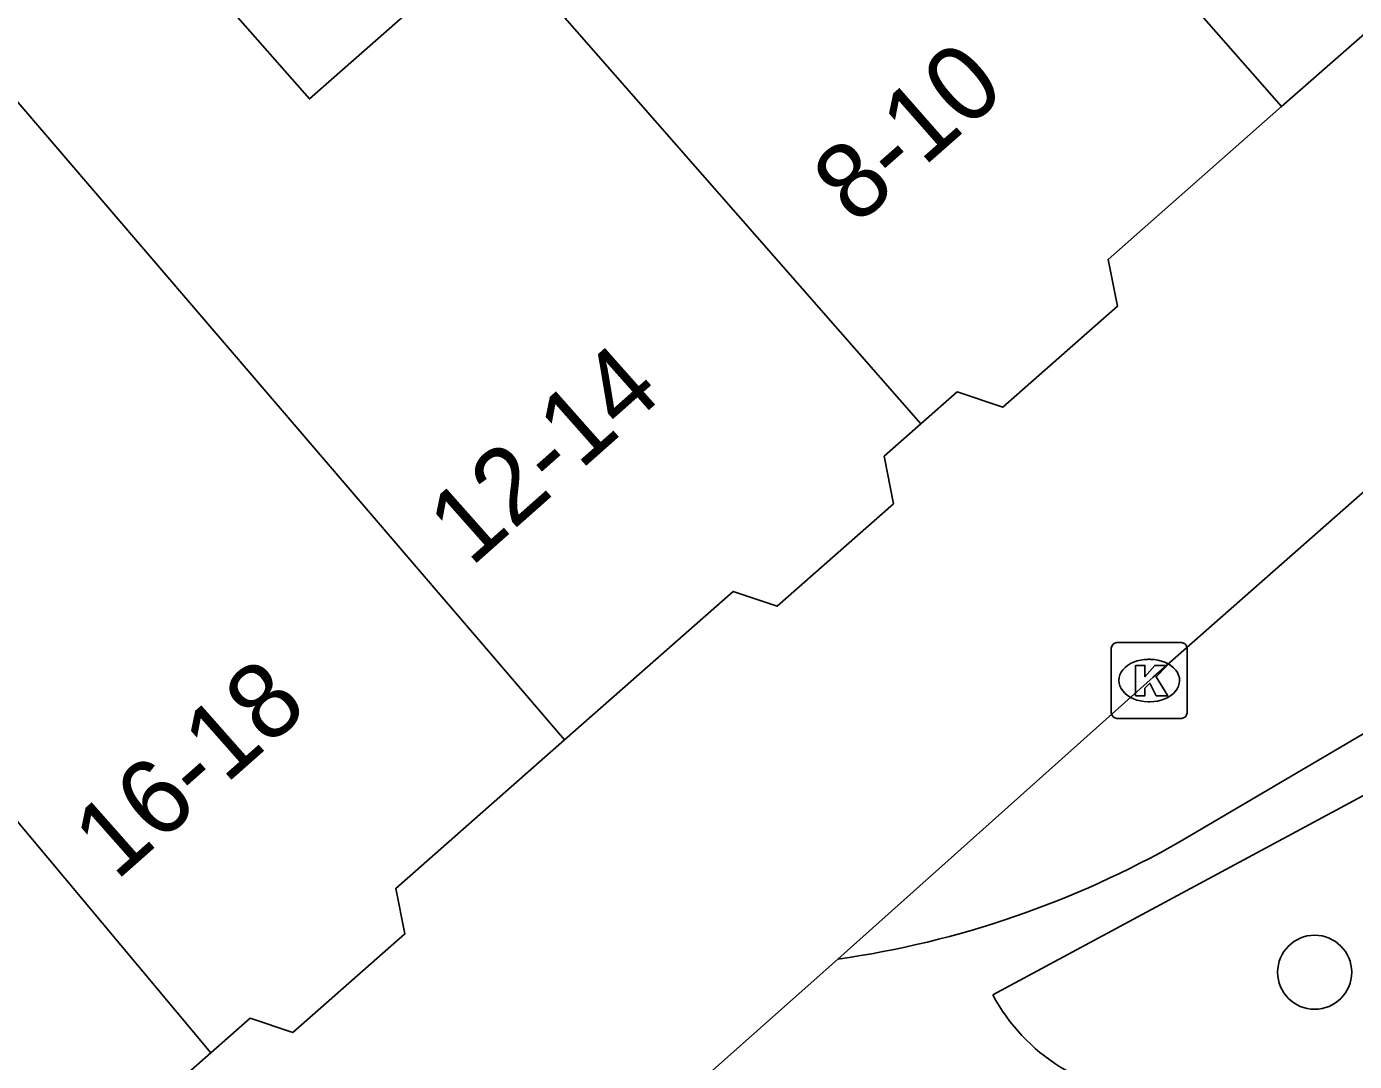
# Model space of a CAD drawing. Extents: x 159961 to 160856, y 382704 to 383353.
# Drawn here: x 160523.05 to 160540.59, y 383049.52 to 383063.19 of the extents above; entities that cross this region are included whole.
import ezdxf

# ---------------------------------------------------------------- set-up
doc = ezdxf.new("R2010")
doc.units = 0
for name, color, linetype in [('IMGEO_Boom', 7, 'Continuous'), ('IMGEO_Kolk', 7, 'Continuous'), ('IMGEO_Pand', 7, 'Continuous'), ('IMGEO_Pand_nummerreeks', 7, 'Continuous'), ('IMGEO_Voetpad_open', 7, 'Continuous')]:
    doc.layers.add(name, color=color, linetype=linetype)

msp = doc.modelspace()

# ---------------------------------------------------------------- linework, layer by layer
at = {"layer": 'IMGEO_Boom'}
msp.add_circle((160540.068, 383050.7), 0.489, dxfattribs=at)
at = {"layer": 'IMGEO_Kolk'}
for p, q in [((160537.382, 383054.127), (160537.382, 383054.979)), ((160537.457, 383055.053), (160538.309, 383055.053)), ((160538.383, 383054.979), (160538.383, 383054.127)), ((160537.87, 383054.833), (160537.895, 383054.833)), ((160537.893, 383054.273), (160537.868, 383054.273)), ((160538.309, 383054.053), (160537.457, 383054.053))]:
    msp.add_line(p, q, dxfattribs=at)
for points in [[(160537.382, 383054.127), (160537.382, 383054.979)], [(160537.457, 383055.053), (160538.309, 383055.053)], [(160538.383, 383054.979), (160538.383, 383054.127)], [(160537.703, 383054.753), (160537.826, 383054.753), (160537.826, 383054.602), (160537.956, 383054.753), (160538.12, 383054.753), (160537.974, 383054.602), (160538.127, 383054.353), (160537.975, 383054.353), (160537.89, 383054.517), (160537.826, 383054.45), (160537.826, 383054.353), (160537.703, 383054.353), (160537.703, 383054.753)], [(160538.309, 383054.053), (160537.457, 383054.053)]]:
    msp.add_lwpolyline(points, dxfattribs=at)
for centre, start, end in [((160537.459, 383054.977), 91.552, 178.448), ((160537.459, 383054.977), 91.552, 178.448), ((160538.307, 383054.977), 1.552, 88.448), ((160538.307, 383054.977), 1.552, 88.448), ((160537.459, 383054.129), 181.552, 268.448), ((160537.459, 383054.129), 181.552, 268.448), ((160538.307, 383054.129), 271.552, 358.448), ((160538.307, 383054.129), 271.552, 358.448)]:
    msp.add_arc(centre, 0.0765, start, end, dxfattribs=at)
for centre, major_axis, ratio, start_param, end_param in [((160537.869, 383054.553), (-0.387, 0.002), 0.722429, 4.712389, 7.853982), ((160537.894, 383054.553), (-0.39, 0.002), 0.717154, 1.570796, 4.712389)]:
    msp.add_ellipse(centre, major_axis=major_axis, ratio=ratio, start_param=start_param, end_param=end_param, dxfattribs=at)
at = {"layer": 'IMGEO_Pand'}
for points in [[(160530.268, 383072.789), (160539.632, 383062.132)], [(160520.95, 383064.512), (160523.35, 383066.624), (160525.951, 383063.668), (160525.713, 383063.459), (160526.791, 383062.234), (160529.228, 383064.379)], [(160539.632, 383062.132), (160541.437, 383063.72), (160542.131, 383062.942), (160545.173, 383065.602)], [(160530.16, 383053.768), (160520.95, 383064.512)], [(160534.867, 383057.942), (160529.228, 383064.379)], [(160534.867, 383057.942), (160535.348, 383058.365), (160535.948, 383058.162), (160537.465, 383059.497), (160537.34, 383060.115), (160539.632, 383062.132)], [(160530.16, 383053.768), (160532.388, 383055.729), (160532.968, 383055.534), (160534.507, 383056.888), (160534.381, 383057.514), (160534.867, 383057.942)], [(160519.966, 383056.235), (160525.489, 383049.638)], [(160525.489, 383049.638), (160526.007, 383050.093), (160526.57, 383049.903), (160528.052, 383051.207), (160527.931, 383051.807), (160530.16, 383053.768)], [(160520.78, 383045.465), (160523.013, 383047.43), (160523.572, 383047.241), (160525.053, 383048.545), (160524.932, 383049.148), (160525.489, 383049.638)]]:
    msp.add_lwpolyline(points, dxfattribs=at)
at = {"layer": 'IMGEO_Voetpad_open'}
for points in [[(160542.574, 383058.683), (160537.937, 383054.599), (160533.771, 383050.874)], [(160541.572, 383054.355), (160538.29, 383052.426)], [(160535.818, 383050.401), (160541.107, 383053.247)], [(160533.771, 383050.874), (160532.081, 383049.37)]]:
    msp.add_lwpolyline(points, dxfattribs=at)
for centre, radius, start, end in [((160531.988, 383063.421), 12.673, 278.0886, 299.8203), ((160538.015, 383051.568), 2.488, 207.97, 268.4555)]:
    msp.add_arc(centre, radius, start, end, dxfattribs=at)

# ---------------------------------------------------------------- texts
at = {"layer": 'IMGEO_Pand_nummerreeks'}
for s, rotation, p in [('8-10', 41.3265, (160534.009, 383060.543)), ('12-14', 41.5604, (160528.924, 383056.04)), ('16-18', 41.488, (160524.237, 383051.895))]:
    msp.add_text(s, height=1, rotation=rotation, dxfattribs=at).set_placement(p)

doc.saveas('drawing.dxf')
